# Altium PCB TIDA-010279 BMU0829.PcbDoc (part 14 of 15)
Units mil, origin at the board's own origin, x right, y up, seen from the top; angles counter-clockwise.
Board outline 11269.69 x 4438.98 mil, 4 copper layers (Top Layer, Signal Layer 1, Signal Layer 2, Bottom Layer), stack 61.6 mil thick; 1494 components, 725 nets, 3766 pads, 2728 vias.
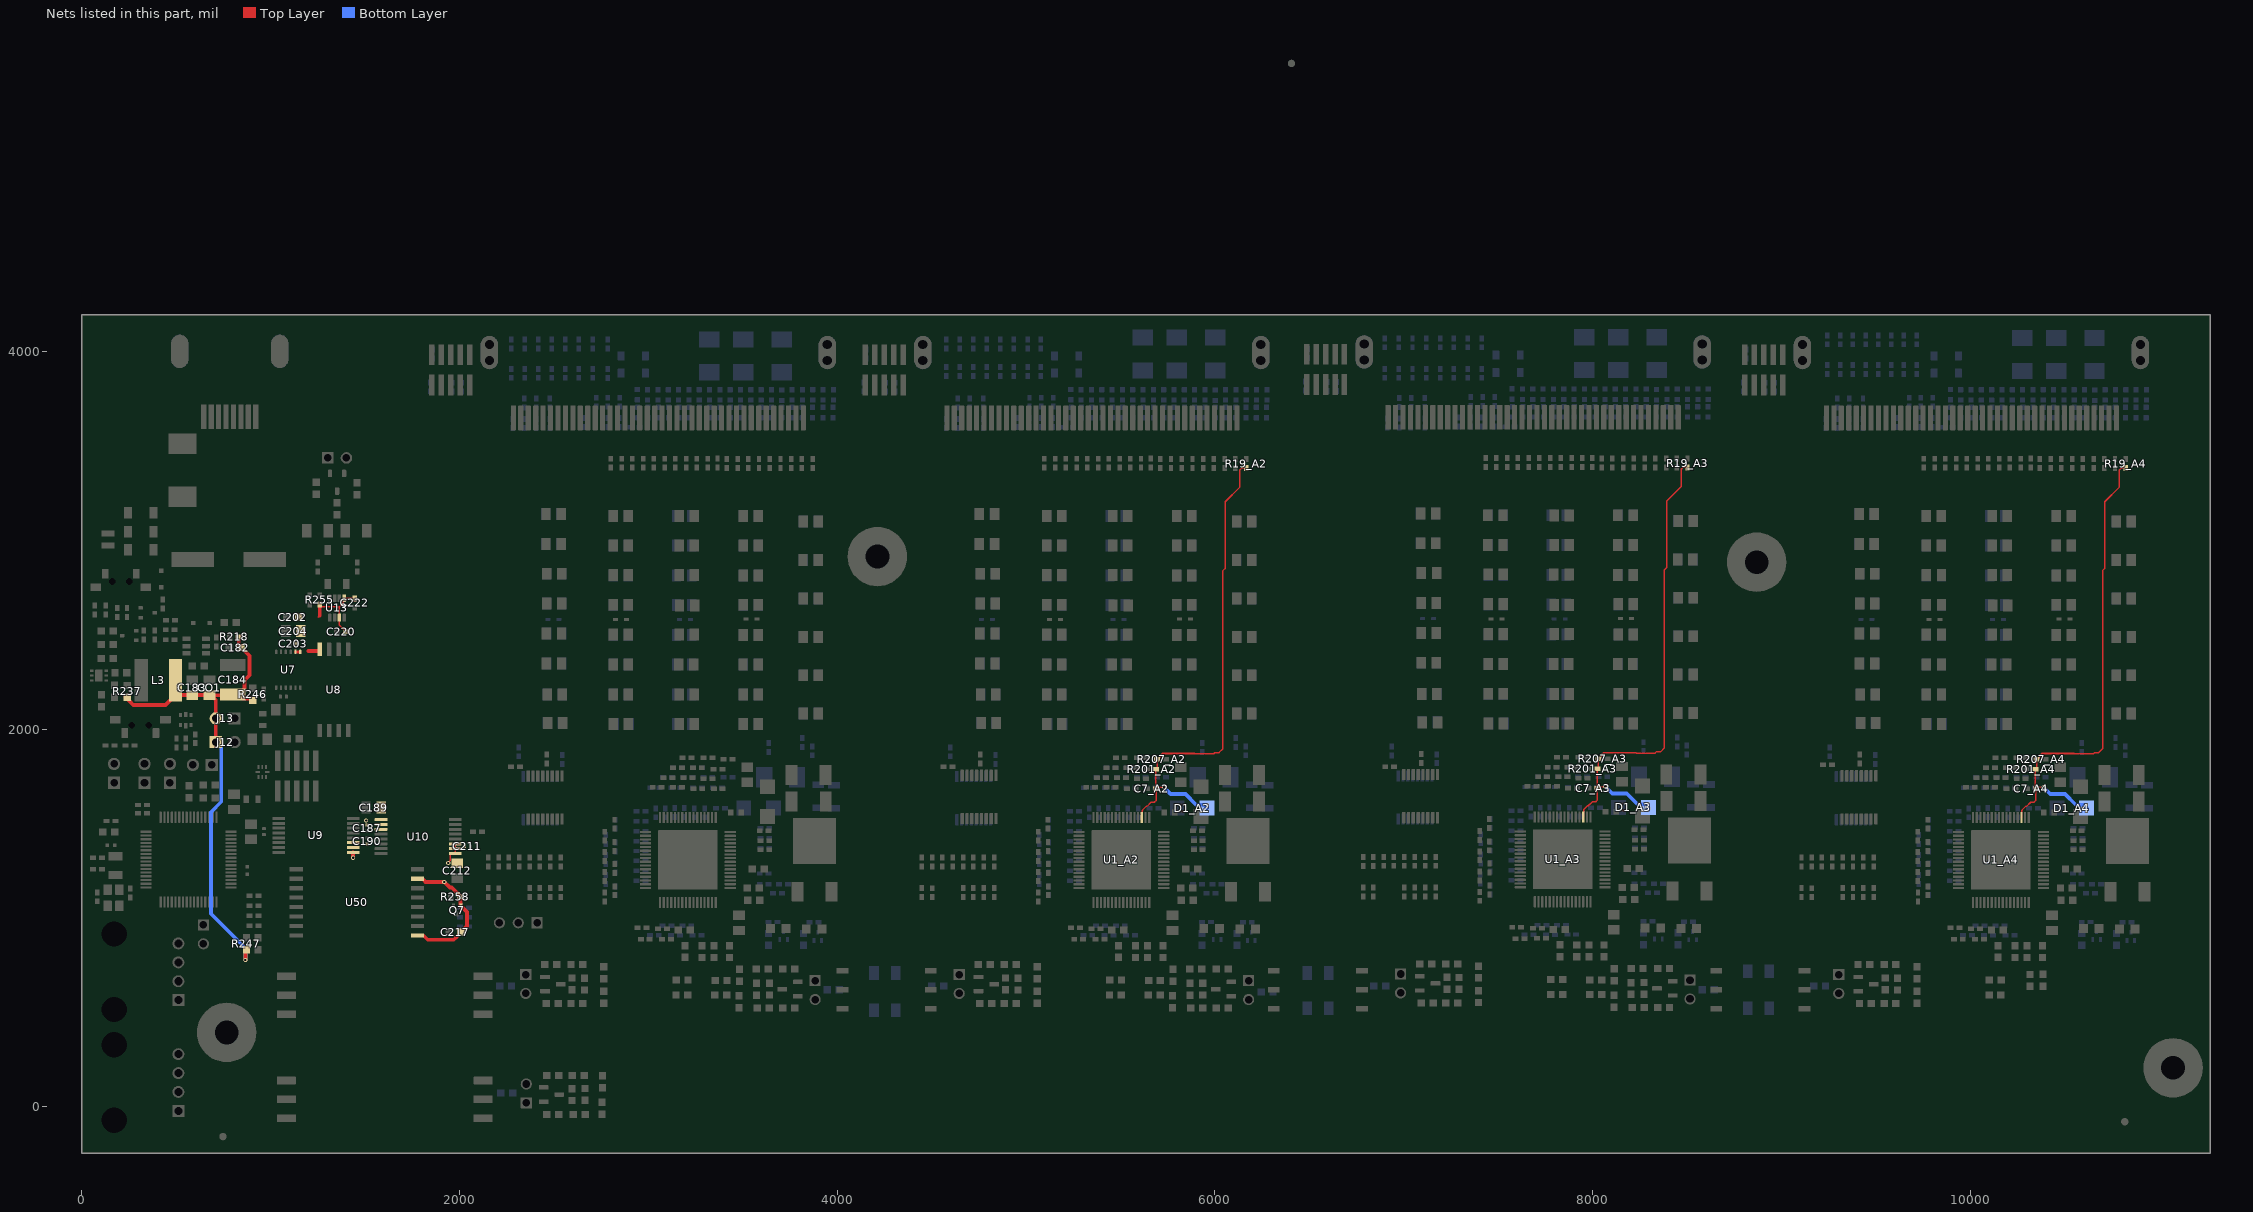
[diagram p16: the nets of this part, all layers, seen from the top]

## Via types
v1: diameter 22.01, hole 12.01, Top Layer to Bottom Layer, tented both sides, 2578 vias
v2: diameter 19.68, hole 7.87, Top Layer to Bottom Layer, tented both sides, 144 vias
v3: diameter 92.52, hole 49.21, Top Layer to Bottom Layer, 4 vias
v4: diameter 19.68, hole 7.87, Top Layer to Bottom Layer, 2 vias

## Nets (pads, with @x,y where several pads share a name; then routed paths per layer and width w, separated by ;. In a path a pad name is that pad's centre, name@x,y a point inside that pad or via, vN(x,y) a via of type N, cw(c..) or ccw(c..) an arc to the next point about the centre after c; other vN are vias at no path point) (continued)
VC18_A2: C7_A2.1 D1_A2.2 R19_A2.2 R201_A2.1 R207_A2.2 U1_A2.3 | length 2622.7
  Top Layer w8: U1_A2.3@5612.75,1531.37 5614.66,1533.27 5614.66,1567.53 5616.47,1569.35 5616.47,1572.07 5635.04,1590.64 5640.25,1590.64 5661.94,1612.33 5678.91,1612.33 5688.08,1621.5 C7_A2.1@5688.08,1683.81 ; R201_A2.1@5687.59,1787.63 R201_A2.1@5693.21,1793.25 ; C7_A2.1@5688.47,1692.33 5729.49,1692.33 v1(5729.7,1692.54) ; R19_A2.2@6165.29,3381.89 6141.48,3381.89 6132.1,3372.52 6132.1,3281.15 6054.11,3203.15 6054.11,2850.84 6042.45,2839.18 6042.45,1896.02 6021.97,1875.54 5999.07,1875.54 5993.22,1869.69 5894.24,1869.69 5893.16,1870.77 5719.79,1870.77 5712.83,1863.81 5712.83,1854.58 5697.81,1839.56 R207_A2.2@5693.87,1839.56 5693.21,1838.9 R201_A2.1@5693.21,1793.25 ; C7_A2.1@5688.73,1683.55 C7_A2.1@5688.73,1690.71 ; C7_A2.1@5688.73,1683.55 C7_A2.1@5688.73,1690.71 ; C7_A2.1@5688.73,1683.55 C7_A2.1@5688.73,1690.71 ; C7_A2.1@5688.73,1690.71 5687.97,1690.71 5687.32,1691.36 5687.32,1787.36 R201_A2.1@5693.21,1793.25
  Bottom Layer w20: v1(5729.7,1692.54) 5765.31,1656.93 5766.22,1656.93 5767.17,1655.98 5843.42,1655.98 5900.1,1599.3 5940.68,1599.3 D1_A2.2@5957.76,1582.22
VC18_A3: C7_A3.1 D1_A3.2 R19_A3.2 R201_A3.1 R207_A3.2 U1_A3.3 | length 2622.7
  Top Layer w8: U1_A3.3@7949.35,1534.57 7951.25,1536.48 7951.25,1570.74 7953.06,1572.55 7953.06,1575.28 7971.63,1593.85 7976.85,1593.85 7998.54,1615.54 8015.51,1615.54 8024.67,1624.7 C7_A3.1@8024.67,1687.01 ; R201_A3.1@8024.19,1790.84 R201_A3.1@8029.81,1796.46 ; C7_A3.1@8025.07,1695.54 8066.09,1695.54 v1(8066.3,1695.74) ; R19_A3.2@8501.88,3385.1 8478.07,3385.1 8468.7,3375.73 8468.7,3284.36 8390.7,3206.36 8390.7,2854.04 8379.05,2842.39 8379.05,1899.23 8358.57,1878.75 8335.67,1878.75 8329.82,1872.89 8230.84,1872.89 8229.76,1873.98 8056.38,1873.98 8049.43,1867.02 8049.43,1857.79 8034.41,1842.77 R207_A3.2@8030.47,1842.77 8029.81,1842.1 R201_A3.1@8029.81,1796.46 ; C7_A3.1@8025.33,1686.76 C7_A3.1@8025.33,1693.92 ; C7_A3.1@8025.33,1686.76 C7_A3.1@8025.33,1693.92 ; C7_A3.1@8025.33,1686.76 C7_A3.1@8025.33,1693.92 ; C7_A3.1@8025.33,1693.92 8024.57,1693.92 8023.92,1694.57 8023.92,1790.57 R201_A3.1@8029.81,1796.46
  Bottom Layer w20: v1(8066.3,1695.74) 8101.91,1660.14 8102.82,1660.14 8103.77,1659.19 8180.02,1659.19 8236.7,1602.51 8277.27,1602.51 D1_A3.2@8294.36,1585.42
VC18_A4: C7_A4.1 D1_A4.2 R19_A4.2 R201_A4.1 R207_A4.2 U1_A4.3 | length 2622.7
  Top Layer w8: U1_A4.3@10269.58,1531.37 10271.48,1533.27 10271.48,1567.54 10273.29,1569.35 10273.29,1572.07 10291.86,1590.64 10297.08,1590.64 10318.77,1612.33 10335.74,1612.33 10344.9,1621.5 C7_A4.1@10344.9,1683.81 ; R201_A4.1@10344.42,1787.63 R201_A4.1@10350.04,1793.25 ; C7_A4.1@10345.3,1692.33 10386.32,1692.33 v1(10386.53,1692.54) ; R19_A4.2@10822.11,3381.89 10798.3,3381.89 10788.93,3372.52 10788.93,3281.15 10710.93,3203.15 10710.93,2850.84 10699.28,2839.18 10699.28,1896.02 10678.79,1875.54 10655.9,1875.54 10650.05,1869.69 10551.07,1869.69 10549.99,1870.77 10376.61,1870.77 10369.66,1863.81 10369.66,1854.58 10354.64,1839.56 R207_A4.2@10350.7,1839.56 10350.04,1838.9 R201_A4.1@10350.04,1793.25 ; C7_A4.1@10345.56,1683.55 C7_A4.1@10345.56,1690.71 ; C7_A4.1@10345.56,1683.55 C7_A4.1@10345.56,1690.71 ; C7_A4.1@10345.56,1683.55 C7_A4.1@10345.56,1690.71 ; C7_A4.1@10345.56,1690.71 10344.8,1690.71 10344.15,1691.36 10344.15,1787.36 R201_A4.1@10350.04,1793.25
  Bottom Layer w20: v1(10386.53,1692.54) 10422.14,1656.93 10423.05,1656.93 10424,1655.98 10500.25,1655.98 10556.93,1599.3 10597.5,1599.3 D1_A4.2@10614.59,1582.22
VCC5V: C182.1 C183.1 C184.1 CO1.1 J12.1 J13.2 L3.2 R218.2 R237.1 R246.1 R247.1 | length 2777.1
  Top Layer w8: R247.1@866.53,826.47 R247.1@871.88,831.82
  Top Layer w20: R237.1@231.03,2172.36 231.03,2171.38 258.78,2143.63 258.78,2141.66 272.92,2127.52 443.55,2127.52 496.86,2180.83 L3.2@496.86,2206.04 ; L3.2@496.86,2257.6 L3.2@496.86,2206.04 ; CO1.1@676.04,2179.27 CO1.1@683.88,2179.27 ; CO1.1@676.04,2180.61 585.31,2180.61 522.29,2180.61 L3.2@496.86,2206.04 ; J12.1@709.8,1931.31 709.36,1931.75 J13.2@709.36,2056.51 709.36,2153.78 CO1.1@683.88,2179.27 ; C184.1@744.42,2193.5 C184.1@744.42,2194.83 ; C184.1@799.53,2182.8 834.96,2182.8 C184.1@807.09,2182.8 ; C184.1@807.09,2185.04 801.31,2179.27 CO1.1@683.88,2179.27 ; R218.2@830.92,2488.31 830.92,2443.74 842.77,2431.89 C182.1@843.75,2431.89 844.73,2431.89 888.45,2388.17 888.45,2284.95 862.52,2259.02 862.52,2216.01 856.46,2209.95 856.46,2204.29 C184.1@840.36,2188.19 ; C184.1@839.78,2181.63 839.78,2177.98 856.46,2161.3 897.75,2161.3 R246.1@905.51,2153.54 ; v1(866.53,777.52) 866.91,777.9 866.91,826.09 R247.1@866.53,826.47
  Bottom Layer w20: J12.1@709.8,1931.31 739.08,1902.03 739.08,1615.06 684.11,1560.08 684.11,1022.34 866.53,839.93 v1(866.53,777.52)
VDD5: C202.1 C203.2 C204.1 C220.2 C222.1 R255.2 U7.7 U7.8 U8.8 U13.3 U13.5 | length 544.6
  Top Layer w8: 1252.32,2593.41 1260.35,2601.44 ; R255.2@1260.35,2660.04 1260.35,2648.98 1364.4,2648.98 U13.3@1364.4,2590.08 1364.4,2549.92 1386.95,2527.37 1386.95,2523.44 1394.76,2515.62 C220.2@1398.7,2515.62 ; 1364.4,2647.26 1385.14,2667.99 1385.14,2687.58 U13.5@1389.99,2692.44 C222.1@1437.65,2692.44
  Top Layer w15: U7.8@1131.9,2408.32 U7.7@1157.49,2408.32
  Top Layer w20: C204.1@1161.18,2513.47 C204.1@1174.53,2500.13 ; 1200.79,2413.91 1258.39,2413.91 1260.2,2415.72 U8.8@1260.2,2421.91 ; 1260.35,2601.44 R255.2@1260.35,2648.98 ; C222.1@1446.1,2691.61 1446.1,2687.68 C222.1@1447.91,2685.87
VStage1_5V: C187.2 C189.1 C190.2 U9.9 U9.10 U9.11 U10.1 U10.2 U10.3 | length 50
  Top Layer w8: C189.1@1585.28,1584.65 C189.1@1600.28,1569.64
  Top Layer w20: v1(1437.01,1318.9) U9.9@1437.01,1347.44
  Bottom Layer w20: v1@1437.01,1318.67 v1(1437.01,1318.9)
  other v1: 1505.91,1515.89
VStage2_5V: C211.2 C212.1 C217.2 Q7.1 R258.2 U10.9 U10.10 U10.11 U50.1 U50.7 | length 803.2
  Top Layer w8: v1(1940.99,1290.66) 1940.99,1294.45 1950.95,1304.41 1950.95,1337.36 1955.02,1341.43 U10.9@1978.48,1341.43 ; U10.9@1975.37,1341.43 1978.35,1344.41 1978.35,1366.88 U10.10@1978.48,1367.02 1978.35,1367.15 1978.35,1392.48 U10.11@1978.48,1392.61
  Top Layer w20: U50.1@1811.02,905.51 1831.76,884.78 1970.1,884.78 1984.41,899.09 1984.41,900.75 2008.86,925.2 2010.83,925.2 2019.53,933.9 2019.53,936.85 2039.47,956.79 2039.47,1031.72 Q7.1@2011.18,1060 ; U50.7@1811.02,1200.79 1820.87,1190.94 v1(1919.29,1190.94) 1949.25,1160.99 1958.78,1160.99 2007.87,1111.89 R258.2@2007.87,1102.36 ; C212.1@1988.19,1290.63 C212.1@1994.69,1290.63 ; Q7.1@2006.14,1065.98 R258.2@2006.14,1102.36
pads on no net: FID1.1 FID2.1 FID3.1 H1.1 H2.1 H3.1 H4.1 H5.0 H6.0 H7.0 H8.0 H9.0 H10.0 H11.0 H12.0 J1_A1.9 J1_A2.9 J1_A3.9 J1_A4.9 J2_A1.9 J2_A1.29 J2_A1.41 J2_A1.42 J2_A2.9 J2_A2.29 J2_A2.41 J2_A2.42 J2_A3.9 J2_A3.29 J2_A3.41 J2_A3.42 J2_A4.9 J2_A4.29 J2_A4.41 J2_A4.42 J5.9 J5.10 J7.3 J7.4 J7.MH1 J7.MH2 J8.1 J8.2 J8.MH1 J8.MH2 J11.6 J11.8 LBL1.0 S1. S2. T1.2 T5.2 U2_A1.7 U2_A2.7 U2_A3.7 U2_A4.7 U3_A1.7 U3_A2.7 U3_A3.7 U3_A4.7 U6.5 U6.7@91.18,2265.47 U6.7@91.18,2300.91 U14.1 U14.3 U14.5 U50.6 U50.11
copper on no net:
  other v3: 519.07,3957.68 1048.6,3957.68 519.07,4042.32 1048.6,4042.32

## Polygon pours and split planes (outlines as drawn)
PGND on Top Layer "TOP_LAYER_PGND_P116" (solid, remove dead copper, pour order 116): 7.55,3722.03 7.55,-148.6 803.65,-148.6 803.65,3722.03
PGND on Top Layer "TOP_LAYER_PGND_P121" (solid, remove dead copper, pour order 121): 799.21,1567.46 799.21,1255.51 936.43,1255.51 936.43,1567.46
GND_A1 on Top Layer "Top Layer-001-AFE1" (solid, remove dead copper, pour order 92): 2106.72,423.23 4045.28,423.23 4045.28,4311.02 1838.84,4311.02 1838.84,4295.38 1811.02,4267.56 1811.02,3670.85 2089.13,3392.74 2117.9,3354.6
GND_A4 on Top Layer "TOP_LAYER_GND_A4_P132" (solid, pour order 132): 10236.22,423.23 10236.22,196.85 2795.28,196.85 2795.28,-98.43 2795.28,-88.58 10360.24,-88.58 10472.44,49.21 10472.44,423.23
GND_A4 on Top Layer "Top Layer-001-AFE1" (solid, remove dead copper, pour order 95): 9058.56,423.23 10997.12,423.23 10997.12,4311.02 8790.68,4311.02 8790.68,4295.38 8762.87,4267.56 8762.87,3670.85 9040.97,3392.74 9069.75,3354.6
PGND on Top Layer "TOP_LAYER_PGND_P118" (solid, remove dead copper, pour order 118): 793.4,2222.16 793.4,1535.29 1218.63,1535.29 1218.63,2222.16
DDGND on Top Layer "TOP_LAYER_DDGND_P120" (solid, remove dead copper, pour order 120): 1257.54,3005.58 1446.1,3005.58 1446.1,3273.89 1257.54,3273.89
PGND on Top Layer "TOP_LAYER_PGND_P119" (solid, remove dead copper, pour order 119): 793.4,2963.17 793.4,2839.08 1081.25,2839.08 1081.25,2963.17
VCC5V on Top Layer "TOP_LAYER_VCC5V_P115" (solid, remove dead copper, pour order 115): 465.33,2209.18 465.33,2151.48 871.28,2151.48 871.28,2209.18
PGND on Top Layer "TOP_LAYER_PGND_P113" (solid, remove dead copper, pour order 113): 739.35,2440.38 739.35,2331.15 873.21,2331.15 873.21,2370.08 808.56,2370.08 808.56,2440.38
PGND on Top Layer "TOP_LAYER_PGND_P112" (solid, remove dead copper, pour order 112): 655.22,2455.05 637.59,2455.05 637.59,2492.45 598.66,2492.45 598.66,2394.78 634.64,2394.78 637.59,2397.74 637.59,2432.78 655.22,2432.78
GND_A2 on Top Layer "Top Layer-001-AFE1" (solid, remove dead copper, pour order 93): 4401.73,423.23 6340.29,423.23 6340.29,4311.02 4133.86,4311.02 4133.86,4295.38 4106.04,4267.56 4106.04,3670.85 4384.15,3392.74 4412.92,3354.6
GND_A3 on Top Layer "Top Layer-001-AFE1" (solid, remove dead copper, pour order 94): 6738.33,426.44 8676.89,426.44 8676.89,4314.23 6470.45,4314.23 6470.45,4298.59 6442.64,4270.77 6442.64,3674.06 6720.74,3395.95 6749.52,3357.81
GND_A1 on Bottom Layer "Bot Layer-GND_AFE1" (solid, remove dead copper, pour order 104): 2096.87,423.23 4035.43,423.23 4035.43,4311.02 1829,4311.02 1829,4295.38 1801.18,4267.56 1801.18,3670.85 2079.29,3392.74 2108.06,3354.6
GND_A4 on Bottom Layer "BOTTOM_LAYER_GND_A4_P133" (solid, pour order 133): 10236.22,442.91 10236.22,196.85 2303.15,196.85 2303.15,-88.58 2312.99,-98.43 2795.28,-98.43 2795.28,-88.58 10360.24,-88.58 10472.44,49.21 10472.44,442.91
GND_Stage2 on Bottom Layer "BOTTOM_LAYER_GND_STAGE2_P129" (solid, pour order 129): 1957.42,1571.46 1948.76,1562.8 1948.76,1302.94 1915.78,1269.97 1837.55,1269.97 1837.55,911.7 1848.04,901.2 2071.78,901.2 2071.78,1568.13 2068.44,1571.46
GND_Stage1 on Bottom Layer "BOTTOM_LAYER_GND_STAGE1_P124" (solid, pour order 124): 1407.48,1633.86 1624.02,1633.86 1624.02,1299.21 1614.17,1289.37 1525.59,1289.37 1525.59,895.67 1505.91,875.98 1348.43,875.98 1348.43,1250 1407.48,1309.06
PGND on Bottom Layer "BOTTOM_LAYER_PGND_P117" (solid, remove dead copper, pour order 117): 157.48,2805.12 24.88,2672.52 24.88,-150 835.29,-150 835.29,2654.14 684.31,2805.12
GND_A3 on Bottom Layer "Bot Layer-GND_AFE1" (solid, remove dead copper, pour order 106): 6728.49,426.44 8667.05,426.44 8667.05,4314.23 6460.61,4314.23 6460.61,4298.59 6432.79,4270.77 6432.79,3674.06 6710.9,3395.95 6739.67,3357.81
GND_A4 on Bottom Layer "Bot Layer-GND_AFE1" (solid, remove dead copper, pour order 107): 9048.72,423.23 10987.28,423.23 10987.28,4311.02 8780.84,4311.02 8780.84,4295.38 8753.02,4267.56 8753.02,3670.85 9031.13,3392.74 9059.9,3354.6
GND_A2 on Bottom Layer "Bot Layer-GND_AFE1" (solid, remove dead copper, pour order 105): 4391.89,423.23 6330.45,423.23 6330.45,4311.02 4124.02,4311.02 4124.02,4295.38 4096.2,4267.56 4096.2,3670.85 4374.31,3392.74 4403.08,3354.6
GND_A1 on Signal Layer 1 "Signal_L2_001-AFE1" (solid, remove dead copper, pour order 100): 2096.87,413.39 4035.43,413.39 4035.43,4301.18 1829,4301.18 1829,4285.53 1801.18,4257.72 1801.18,3661.01 2079.29,3382.9 2108.06,3344.76
GND_A4 on Signal Layer 1 "SIGNAL_LAYER_1_GND_A4_P109" (solid, pour order 109): 10236.22,442.91 10236.22,196.85 2303.15,196.85 2303.15,-88.58 2312.99,-98.43 2795.28,-98.43 2795.28,-88.58 10360.24,-88.58 10472.44,49.21 10472.44,442.91
GND_Stage2 on Signal Layer 1 "SIGNAL_LAYER_1_GND_STAGE2_P128" (solid, pour order 128): 1957.48,1573.62 1948.82,1564.96 1948.82,1305.1 1915.84,1272.13 1837.61,1272.13 1837.61,913.86 1848.1,903.36 2071.84,903.36 2071.84,1570.29 2068.5,1573.62
GND_Stage1 on Signal Layer 1 "SIGNAL_LAYER_1_GND_STAGE1_P126" (solid, pour order 126): 1404.5,1634.44 1621.04,1634.44 1621.04,1299.8 1611.2,1289.95 1522.61,1289.95 1522.61,896.25 1502.93,876.57 1345.45,876.57 1345.45,1250.58 1404.5,1309.64
GND_A2 on Signal Layer 1 "Signal_L2_001-AFE1" (solid, remove dead copper, pour order 101): 4391.89,413.39 6330.45,413.39 6330.45,4301.18 4124.02,4301.18 4124.02,4285.53 4096.2,4257.72 4096.2,3661.01 4374.31,3382.9 4403.08,3344.76
GND_A3 on Signal Layer 1 "Signal_L2_001-AFE1" (solid, remove dead copper, pour order 102): 6728.49,416.59 8667.05,416.59 8667.05,4304.39 6460.61,4304.39 6460.61,4288.74 6432.79,4260.92 6432.79,3664.22 6710.9,3386.11 6739.67,3347.96
GND_A4 on Signal Layer 1 "Signal_L2_001-AFE1" (solid, remove dead copper, pour order 103): 9048.72,413.39 10987.28,413.39 10987.28,4301.18 8780.84,4301.18 8780.84,4285.53 8753.02,4257.72 8753.02,3661.01 9031.13,3382.9 9059.9,3344.76
GND_A1 on Signal Layer 2 "Signal_L3_001-AFE1" (solid, remove dead copper, pour order 96): 2097.3,423.79 4035.43,423.79 4035.43,4291.34 1829,4291.34 1829,4275.69 1815.09,4261.78 1815.09,3637.26 2079.29,3373.06 2108.06,3334.91 2108.06,3244.31
GND_A4 on Signal Layer 2 "SIGNAL_LAYER_2_GND_A4_P131" (solid, pour order 131): 10236.22,442.91 10236.22,196.85 2303.15,196.85 2303.15,-88.58 2312.99,-98.43 2795.28,-98.43 2795.28,-88.58 10360.24,-88.58 10472.44,49.21 10472.44,442.91
VStage2_5V on Signal Layer 2 "SIGNAL_LAYER_2_VSTAGE2_5V_P130" (solid, pour order 130): 1957.78,1572.53 1949.11,1563.87 1949.11,1304.01 1916.14,1271.03 1837.9,1271.03 1837.9,912.77 1848.4,902.27 2072.14,902.27 2072.14,1569.19 2068.8,1572.53
VStage1_5V on Signal Layer 2 "SIGNAL_LAYER_2_VSTAGE1_5V_P127" (solid, pour order 127): 1408.47,1633.52 1625.01,1633.52 1625.01,1298.87 1615.16,1289.03 1526.58,1289.03 1526.58,895.33 1506.9,875.64 1349.42,875.64 1349.42,1249.66 1408.47,1308.71
PGND on Signal Layer 2 "SIGNAL_LAYER_2_PGND_P114" (solid, remove dead copper, pour order 114): 49.21,3435.53 49.21,-127.95 840.88,-127.95 840.88,3435.53
GND_A2 on Signal Layer 2 "Signal_L3_001-AFE1" (solid, remove dead copper, pour order 97): 4392.31,423.79 6330.45,423.79 6330.45,4291.34 4124.02,4291.34 4124.02,4275.69 4110.11,4261.78 4110.11,3637.26 4374.31,3373.06 4403.08,3334.91 4403.08,3244.31
GND_A3 on Signal Layer 2 "Signal_L3_001-AFE1" (solid, remove dead copper, pour order 98): 6728.91,426.99 8667.05,426.99 8667.05,4294.55 6460.61,4294.55 6460.61,4278.9 6446.7,4264.99 6446.7,3640.47 6710.9,3376.27 6739.67,3338.12 6739.67,3247.51
GND_A4 on Signal Layer 2 "Signal_L3_001-AFE1" (solid, remove dead copper, pour order 99): 9049.14,423.79 10987.28,423.79 10987.28,4291.34 8780.84,4291.34 8780.84,4275.69 8766.93,4261.78 8766.93,3637.26 9031.13,3373.06 9059.9,3334.91 9059.9,3244.31

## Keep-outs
Keep-Out Layer:
  text ".Layer_Name" at 577,-858.49 h60

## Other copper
Top Layer:
  region net GND_Stage2: 1840.55,1269.68 1846.38,1275.51 1913.01,1275.51 1953.63,1234.89 2035.25,1234.89 2049.04,1248.68 2052.39,1245.33 2052.39,1180.85 1957.36,1180.85 1938.72,1199.49 1938.72,1217.38 1901.46,1254.64 1841.08,1254.64
  region net GND_Stage2: 1948.82,1574.8 2086.61,1574.8 2086.61,1181.1 2047.7,1181.1 2047.7,1302.55 2047.7,1417.32 1948.82,1417.32
  region net DDGND: 972.31,2654.14 972.31,2391.09 1115.75,2391.09 1115.75,2654.14
  region net NetC205_1: 996.3,2183.12 996.3,2069.86 1058.69,2069.86 1058.69,2183.12
  region net GND_Stage1: 1407.48,1624.02 1407.48,1417.32 1522.11,1417.32 1531.48,1407.95 1531.38,1407.85 1531.38,1374.74 1476.06,1319.42 1476.06,1293.9 1479.19,1290.77 1480.4,1291.98 1625.67,1291.98 1625.67,1326.41 1617.66,1334.41 1618.12,1334.86 1618.12,1451.14 1527.06,1451.14 1524.04,1454.16 1513.96,1467.45 1480.4,1467.45 1470.2,1477.64 1470.2,1542.86 1479.99,1552.65 1480.83,1551.81 1534.7,1551.81 1534.7,1619.52 1527.78,1626.43 1407.78,1626.43
  pour cut-out: 1407.48,1870.08 1230.31,1870.08 1171.26,1811.02 1171.26,875.98 1171.26,-236.22 1407.48,-236.22
  region net VStage1_5V: 1404.34,1403.95 1404.88,1403.41 1404.88,1338.58 1466.54,1338.58 1505.91,1377.95 1515.75,1387.8 1521.34,1387.8 1521.33,1387.81 1521.33,1405.67 1407.42,1405.67 1405.56,1407.52
  region net VStage1_5V: 1616.05,1618.41 1616.05,1461.42 1611.21,1460.24 1553.33,1460.24 1529.69,1483.87 1502.88,1483.87 1497.12,1489.63 1497.12,1523.57 1539.39,1523.57 1557.04,1541.22 1557.04,1618.41
  region net PGND: 1072.83,2234.25 1072.83,2175.2 1092.52,2155.51 1220.47,2155.51 1220.47,2234.25
  pour cut-out: 76.09,1185.12 44.69,1153.72 44.69,1056.01 68.92,1031.78 247.67,1031.78 277.18,1061.29 277.18,1151.43 245.03,1183.57
  pour cut-out: 974.41,2389.81 974.41,2236.18 1271.01,2236.18 1271.01,2387.09
  region net PGND: 1014.62,1455.98 1014.62,1339.29 1082.68,1339.29 1082.68,1455.98
  region net PGND: 1056.3,2053.8 1056.3,2003.4 1120.86,2003.4 1120.86,2053.8
  region net NetC213_1: 1024.28,1468.18 1024.28,1505.8 854.54,1505.8 854.54,1468.18
  pour cut-out: 63.5,1363.16 32.6,1332.27 32.6,1237.56 67.62,1202.54 238.54,1202.54 272,1236.01 272,1332.6 243.08,1361.52
  region net VDD5: 1128.69,2619.16 1128.69,2390.64 1268.68,2390.64 1268.68,2619.16
  region net VStage2_5V: 1937.47,1400.96 1937.47,1269.69 2033.57,1269.68 2033.57,1400.96
  pour cut-out: 849.09,1672.47 849.09,1595.35 961.71,1595.35 961.71,1671.44
  region net DDGND: 972.31,2645.2 1219,2645.2 1219,2675.78 972.31,2675.78
  pour cut-out: 1087.56,2843.23 1257.54,2843.23 1257.54,3435.53 1092.99,3435.53
  pour cut-out: 1255.26,2670.92 1255.26,2842.37 803.52,2842.37 803.52,2675.06
  pour cut-out: 976.11,2677.86 806.62,2677.86 806.63,2233.05 972.03,2233.05
  region net PGND: 851.87,1252.99 1023.99,1252.99 1023.99,1455.16 851.87,1455.16
  pour cut-out: 1830.71,834.1 2815.7,834.1 2905.55,744.25 3458.36,744.25 3458.36,747.7 3508.46,797.8 4063.31,797.8 4063.31,413.39 1830.71,413.39
  pour cut-out: 3405.51,1289.37 3612.2,1289.37 3622.05,1289.37 3641.73,1279.53 3641.73,1151.57 3622.05,1131.89 3503.94,1131.89 3464.57,1171.26 3464.57,1181.1 3405.51,1181.1 3405.51,1299.21 3395.67,1299.21 3395.67,1171.26 3405.51,1171.26 3454.72,1171.26 3503.94,1122.05 3622.05,1122.05 3651.57,1151.57 3651.57,1279.53 3622.05,1299.21 3612.2,1299.21 3405.51,1299.21
  region net CELL0_A1: 2371.07,2251.95 2495.94,2251.95 2495.94,1980.81 2371.07,1980.81
  region net CELL1_A1: 2370.87,2560.01 2495.74,2560.01 2495.74,2288.87 2370.87,2288.87
  region net CELL2_A1: 2370.87,2877.38 2495.74,2877.38 2495.74,2606.24 2370.87,2606.24
  region net CB0_A1: 2510.32,2251.95 2635.19,2251.95 2635.19,1980.81 2510.32,1980.81
  region net CB1_A1: 2511.71,2560.01 2636.58,2560.01 2636.58,2288.87 2511.71,2288.87
  region net CB2_A1: 2511.71,2877.38 2636.58,2877.38 2636.58,2606.24 2511.71,2606.24
  region net CELL4_A1: 2722.14,2242.64 2847.01,2242.64 2847.01,1971.5 2722.14,1971.5
  region net CELL5_A1: 2722.14,2559.36 2847.01,2559.36 2847.01,2288.22 2722.14,2288.22
  region net CB4_A1: 2863.18,2242.64 2988.05,2242.64 2988.05,1971.5 2863.18,1971.5
  region net CB5_A1: 2863.18,2559.36 2988.05,2559.36 2988.05,2288.22 2863.18,2288.22
  region net CELL6_A1: 2722.14,2876.08 2847.01,2876.08 2847.01,2604.94 2722.14,2604.94
  region net CB6_A1: 2863.18,2876.08 2988.05,2876.08 2988.05,2604.94 2863.18,2604.94
  region net CELL8_A1: 3077.16,2242.76 3202.03,2242.76 3202.03,1971.62 3077.16,1971.62
  region net CELL10_A1: 3077.16,2877.5 3202.03,2877.5 3202.03,2606.36 3077.16,2606.36
  region net CELL9_A1: 3079.07,2561.48 3203.94,2561.48 3203.94,2290.34 3079.07,2290.34
  region net CELL3_A1: 2495.75,2923.45 2370.87,2923.45 2370.87,3194.59 2495.75,3194.59
  region net CB3_A1: 2636.59,2923.45 2511.72,2923.45 2511.72,3194.59 2636.59,3194.59
  region net CELL7_A1: 2847.01,2921.66 2722.14,2921.66 2722.14,3192.8 2847.01,3192.8
  region net CB7_A1: 2988.05,2921.66 2863.18,2921.66 2863.18,3192.8 2988.05,3192.8
  region net CELL11_A1: 3077.16,3195.54 3202.03,3195.54 3202.03,2924.4 3077.16,2924.4
  region net CB8_A1: 3214.14,2242.76 3339.02,2242.76 3339.02,1971.62 3214.14,1971.62
  region net CB9_A1: 3214.14,2560.13 3339.02,2560.13 3339.02,2288.99 3214.14,2288.99
  pour cut-out: 4064.96,4246.79 4064.96,1201.43 3671.26,1201.43 3671.26,1481.76 3022.52,1481.76 3022.52,1138.81 2844.39,1141.69 2844.39,1136.74 2724.59,1016.94 2566.67,1016.94 2566.67,3341.05 2786.12,3341.05 2841.36,3396.3 2841.36,3512.81 2954.83,3512.81 2991.36,3549.34 2991.36,4243.33 2994.82,4246.79
  region net CELL12_A1: 3416.41,2241.78 3541.29,2241.78 3541.29,1970.64 3416.41,1970.64
  region net CELL13_A1: 3417.1,2560.13 3541.98,2560.13 3541.98,2288.99 3417.1,2288.99
  region net CB12_A1: 3554.09,2242.76 3678.96,2242.76 3678.96,1971.62 3554.09,1971.62
  region net CELL16_A1: 3772.15,2361.15 3860.17,2361.15 3860.17,1979.4 3772.15,1979.4
  region net CB16_A1: 3870.59,2358.65 3958.61,2358.65 3958.61,1979.4 3870.59,1979.4
  region net CB13_A1: 3554.09,2560.13 3678.96,2560.13 3678.96,2288.99 3554.09,2288.99
  region net CELL17_A1: 3771.83,2779.69 3859.85,2779.69 3859.85,2397.94 3771.83,2397.94
  region net CB17_A1: 3870.27,2777.19 3958.29,2777.19 3958.29,2397.94 3870.27,2397.94
  region net CELL0_A2: 4666.08,2251.95 4790.96,2251.95 4790.96,1980.81 4666.08,1980.81
  region net CELL1_A2: 4665.88,2560.01 4790.76,2560.01 4790.76,2288.87 4665.88,2288.87
  region net CB10_A1: 3214.14,2877.5 3339.02,2877.5 3339.02,2606.36 3214.14,2606.36
  region net CB11_A1: 3214.14,3194.87 3339.02,3194.87 3339.02,2923.73 3214.14,2923.73
  region net CELL14_A1: 3417.1,2877.5 3541.98,2877.5 3541.98,2606.36 3417.1,2606.36
  region net CELL15_A1: 3417.1,3195.54 3541.98,3195.54 3541.98,2924.4 3417.1,2924.4
  region net CB14_A1: 3554.09,2877.5 3678.96,2877.5 3678.96,2606.36 3554.09,2606.36
  region net CB15_A1: 3554.09,3194.87 3678.96,3194.87 3678.96,2923.73 3554.09,2923.73
  region net CELL18_A1: 3770.96,3198.23 3858.98,3198.23 3858.98,2816.48 3770.96,2816.48
  region net CB18_A1: 3869.4,3195.73 3957.42,3195.73 3957.42,2816.48 3869.4,2816.48
  region net CELL2_A2: 4665.88,2877.38 4790.76,2877.38 4790.76,2606.24 4665.88,2606.24
  region net CELL3_A2: 4790.76,2923.45 4665.89,2923.45 4665.89,3194.59 4790.76,3194.59
  pour cut-out: 4125.72,834.1 5110.71,834.1 5200.57,744.25 5753.37,744.25 5753.37,747.7 5803.48,797.8 6358.33,797.8 6358.33,413.39 4125.72,413.39
  pour cut-out: 5700.53,1289.37 5907.22,1289.37 5917.06,1289.37 5936.75,1279.53 5936.75,1151.57 5917.06,1131.89 5798.95,1131.89 5759.58,1171.26 5759.58,1181.1 5700.53,1181.1 5700.53,1299.21 5690.69,1299.21 5690.69,1171.26 5700.53,1171.26 5749.74,1171.26 5798.95,1122.05 5917.06,1122.05 5946.59,1151.57 5946.59,1279.53 5917.06,1299.21 5907.22,1299.21 5700.53,1299.21
  pour cut-out: 6462.32,837.31 7447.31,837.31 7537.16,747.45 8089.97,747.45 8089.97,750.9 8140.08,801.01 8694.92,801.01 8694.92,416.59 6462.32,416.59
  pour cut-out: 8037.12,1292.58 8243.82,1292.58 8253.66,1292.58 8273.34,1282.74 8273.34,1154.78 8253.66,1135.1 8135.55,1135.1 8096.18,1174.47 8096.18,1184.31 8037.12,1184.31 8037.12,1302.42 8027.28,1302.42 8027.28,1174.47 8037.12,1174.47 8086.34,1174.47 8135.55,1125.26 8253.66,1125.26 8283.19,1154.78 8283.19,1282.74 8253.66,1302.42 8243.82,1302.42 8037.12,1302.42
  pour cut-out: 8782.55,834.1 9767.54,834.1 9857.39,744.25 10236.22,744.25 10236.22,413.39 8782.55,413.39
  pour cut-out: 10357.35,1289.37 10564.05,1289.37 10573.89,1289.37 10593.57,1279.53 10593.57,1151.57 10573.89,1131.89 10455.78,1131.89 10416.41,1171.26 10416.41,1181.1 10357.35,1181.1 10357.35,1299.21 10347.51,1299.21 10347.51,1171.26 10357.35,1171.26 10406.57,1171.26 10455.78,1122.05 10573.89,1122.05 10603.42,1151.57 10603.42,1279.53 10573.89,1299.21 10564.05,1299.21 10357.35,1299.21
  region net CELL4_A2: 5017.15,2242.64 5142.03,2242.64 5142.03,1971.5 5017.15,1971.5
  region net CB0_A2: 4805.33,2251.95 4930.21,2251.95 4930.21,1980.81 4805.33,1980.81
  region net CB4_A2: 5158.19,2242.64 5283.07,2242.64 5283.07,1971.5 5158.19,1971.5
  region net CELL8_A2: 5372.17,2242.76 5497.05,2242.76 5497.05,1971.62 5372.17,1971.62
  region net CB8_A2: 5509.16,2242.76 5634.03,2242.76 5634.03,1971.62 5509.16,1971.62
  region net CELL12_A2: 5711.43,2241.78 5836.3,2241.78 5836.3,1970.64 5711.43,1970.64
  region net CB12_A2: 5849.1,2242.76 5973.98,2242.76 5973.98,1971.62 5849.1,1971.62
  region net CELL5_A2: 5017.15,2559.36 5142.03,2559.36 5142.03,2288.22 5017.15,2288.22
  region net CB1_A2: 4806.73,2560.01 4931.6,2560.01 4931.6,2288.87 4806.73,2288.87
  region net CELL6_A2: 5017.15,2876.08 5142.03,2876.08 5142.03,2604.94 5017.15,2604.94
  region net CB2_A2: 4806.73,2877.38 4931.6,2877.38 4931.6,2606.24 4806.73,2606.24
  region net CB5_A2: 5158.19,2559.36 5283.07,2559.36 5283.07,2288.22 5158.19,2288.22
  region net CB6_A2: 5158.19,2876.08 5283.07,2876.08 5283.07,2604.94 5158.19,2604.94
  region net CELL7_A2: 5142.03,2921.66 5017.15,2921.66 5017.15,3192.8 5142.03,3192.8
  region net CB3_A2: 4931.61,2923.45 4806.73,2923.45 4806.73,3194.59 4931.61,3194.59
  region net CB7_A2: 5283.07,2921.66 5158.19,2921.66 5158.19,3192.8 5283.07,3192.8
  region net CB9_A2: 5509.16,2560.13 5634.03,2560.13 5634.03,2288.99 5509.16,2288.99
  region net CELL9_A2: 5374.08,2561.48 5498.96,2561.48 5498.96,2290.34 5374.08,2290.34
  pour cut-out: 6359.98,4246.79 6359.98,1201.43 5966.28,1201.43 5966.28,1481.76 5317.54,1481.76 5317.54,1138.81 5139.4,1141.69 5139.4,1136.74 5019.61,1016.94 4861.69,1016.94 4861.69,3341.05 5081.14,3341.05 5136.38,3396.3 5136.38,3512.81 5249.85,3512.81 5286.38,3549.34 5286.38,4243.33 5289.84,4246.79
  region net CELL10_A2: 5372.17,2877.5 5497.05,2877.5 5497.05,2606.36 5372.17,2606.36
  region net CB10_A2: 5509.16,2877.5 5634.03,2877.5 5634.03,2606.36 5509.16,2606.36
  region net CELL13_A2: 5712.12,2560.13 5836.99,2560.13 5836.99,2288.99 5712.12,2288.99
  region net CB13_A2: 5849.1,2560.13 5973.98,2560.13 5973.98,2288.99 5849.1,2288.99
  region net CB14_A2: 5849.1,2877.5 5973.98,2877.5 5973.98,2606.36 5849.1,2606.36
  region net CB11_A2: 5509.16,3194.87 5634.03,3194.87 5634.03,2923.73 5509.16,2923.73
  region net CELL11_A2: 5372.17,3195.54 5497.05,3195.54 5497.05,2924.4 5372.17,2924.4
  region net CELL14_A2: 5712.12,2877.5 5836.99,2877.5 5836.99,2606.36 5712.12,2606.36
  region net CB15_A2: 5849.1,3194.87 5973.98,3194.87 5973.98,2923.73 5849.1,2923.73
  region net CELL15_A2: 5712.12,3195.54 5836.99,3195.54 5836.99,2924.4 5712.12,2924.4
  region net CB16_A2: 6165.61,2358.65 6253.62,2358.65 6253.62,1979.4 6165.61,1979.4
  region net CELL16_A2: 6067.17,2361.15 6155.19,2361.15 6155.19,1979.4 6067.17,1979.4
  region net CELL0_A3: 7002.68,2255.16 7127.56,2255.16 7127.56,1984.02 7002.68,1984.02
  region net CELL4_A3: 7353.75,2245.85 7478.62,2245.85 7478.62,1974.71 7353.75,1974.71
  region net CB0_A3: 7141.93,2255.16 7266.8,2255.16 7266.8,1984.02 7141.93,1984.02
  region net CB4_A3: 7494.79,2245.85 7619.67,2245.85 7619.67,1974.71 7494.79,1974.71
  region net CELL8_A3: 7708.77,2245.97 7833.65,2245.97 7833.65,1974.83 7708.77,1974.83
  region net CB17_A2: 6165.29,2777.19 6253.3,2777.19 6253.3,2397.94 6165.29,2397.94
  region net CELL17_A2: 6066.85,2779.69 6154.87,2779.69 6154.87,2397.94 6066.85,2397.94
  region net CELL1_A3: 7002.48,2563.22 7127.35,2563.22 7127.35,2292.08 7002.48,2292.08
  region net CB1_A3: 7143.32,2563.22 7268.2,2563.22 7268.2,2292.08 7143.32,2292.08
  region net CELL2_A3: 7002.48,2880.59 7127.35,2880.59 7127.35,2609.45 7002.48,2609.45
  region net CB2_A3: 7143.32,2880.59 7268.2,2880.59 7268.2,2609.45 7143.32,2609.45
  region net CB18_A2: 6164.42,3195.73 6252.43,3195.73 6252.43,2816.48 6164.42,2816.48
  region net CELL18_A2: 6065.98,3198.23 6154,3198.23 6154,2816.48 6065.98,2816.48
  region net CELL3_A3: 7127.36,2926.66 7002.48,2926.66 7002.48,3197.8 7127.36,3197.8
  region net CB3_A3: 7268.2,2926.66 7143.33,2926.66 7143.33,3197.8 7268.2,3197.8
  region net CB5_A3: 7494.79,2562.57 7619.67,2562.57 7619.67,2291.43 7494.79,2291.43
  region net CELL5_A3: 7353.75,2562.57 7478.62,2562.57 7478.62,2291.43 7353.75,2291.43
  region net CELL6_A3: 7353.75,2879.29 7478.62,2879.29 7478.62,2608.15 7353.75,2608.15
  region net CB6_A3: 7494.79,2879.29 7619.67,2879.29 7619.67,2608.15 7494.79,2608.15
  region net CELL9_A3: 7710.68,2564.69 7835.55,2564.69 7835.55,2293.55 7710.68,2293.55
  region net CELL10_A3: 7708.77,2880.71 7833.65,2880.71 7833.65,2609.57 7708.77,2609.57
  region net CELL7_A3: 7478.62,2924.86 7353.75,2924.86 7353.75,3196.01 7478.62,3196.01
  region net CB7_A3: 7619.67,2924.86 7494.79,2924.86 7494.79,3196.01 7619.67,3196.01
  region net CELL11_A3: 7708.77,3198.75 7833.65,3198.75 7833.65,2927.61 7708.77,2927.61
  region net CB8_A3: 7845.75,2245.97 7970.63,2245.97 7970.63,1974.83 7845.75,1974.83
  region net CELL12_A3: 8048.03,2244.99 8172.9,2244.99 8172.9,1973.85 8048.03,1973.85
  region net CB12_A3: 8185.7,2245.97 8310.57,2245.97 8310.57,1974.83 8185.7,1974.83
  region net CELL16_A3: 8403.77,2364.35 8491.78,2364.35 8491.78,1982.6 8403.77,1982.6
  region net CB16_A3: 8502.2,2361.85 8590.22,2361.85 8590.22,1982.6 8502.2,1982.6
  region net CELL0_A4: 9322.91,2251.95 9447.79,2251.95 9447.79,1980.81 9322.91,1980.81
  region net CB0_A4: 9462.16,2251.95 9587.03,2251.95 9587.03,1980.81 9462.16,1980.81
  region net CB9_A3: 7845.75,2563.34 7970.63,2563.34 7970.63,2292.2 7845.75,2292.2
  region net CELL13_A3: 8048.72,2563.34 8173.59,2563.34 8173.59,2292.2 8048.72,2292.2
  pour cut-out: 8696.57,4250 8696.57,1204.64 8302.87,1204.64 8302.87,1484.97 7654.13,1484.97 7654.13,1142.01 7476,1144.89 7476,1139.94 7356.2,1020.15 7198.29,1020.15 7198.29,3344.26 7417.73,3344.26 7472.98,3399.51 7472.98,3516.02 7586.44,3516.02 7622.98,3552.55 7622.98,4246.54 7626.44,4250
  region net CB13_A3: 8185.7,2563.34 8310.57,2563.34 8310.57,2292.2 8185.7,2292.2
  region net CB10_A3: 7845.75,2880.71 7970.63,2880.71 7970.63,2609.57 7845.75,2609.57
  region net CELL14_A3: 8048.72,2880.71 8173.59,2880.71 8173.59,2609.57 8048.72,2609.57
  region net CB11_A3: 7845.75,3198.08 7970.63,3198.08 7970.63,2926.93 7845.75,2926.93
  region net CELL15_A3: 8048.72,3198.75 8173.59,3198.75 8173.59,2927.61 8048.72,2927.61
  region net CB14_A3: 8185.7,2880.71 8310.57,2880.71 8310.57,2609.57 8185.7,2609.57
  region net CELL18_A3: 8402.58,3201.44 8490.59,3201.44 8490.59,2819.69 8402.58,2819.69
  region net CB15_A3: 8185.7,3198.08 8310.57,3198.08 8310.57,2926.93 8185.7,2926.93
  region net CB17_A3: 8501.88,2780.4 8589.9,2780.4 8589.9,2401.15 8501.88,2401.15
  region net CELL17_A3: 8403.45,2782.9 8491.46,2782.9 8491.46,2401.15 8403.45,2401.15
  region net CELL1_A4: 9322.71,2560.01 9447.58,2560.01 9447.58,2288.87 9322.71,2288.87
  region net CB1_A4: 9463.55,2560.01 9588.43,2560.01 9588.43,2288.87 9463.55,2288.87
  region net CELL2_A4: 9322.71,2877.38 9447.58,2877.38 9447.58,2606.24 9322.71,2606.24
  region net CB18_A3: 8501.01,3198.94 8589.03,3198.94 8589.03,2819.69 8501.01,2819.69
  region net CB2_A4: 9463.55,2877.38 9588.43,2877.38 9588.43,2606.24 9463.55,2606.24
  region net CELL3_A4: 9447.59,2923.45 9322.71,2923.45 9322.71,3194.59 9447.59,3194.59
  region net CB3_A4: 9588.43,2923.45 9463.56,2923.45 9463.56,3194.59 9588.43,3194.59
  region net CELL4_A4: 9673.98,2242.64 9798.85,2242.64 9798.85,1971.5 9673.98,1971.5
  region net CB4_A4: 9815.02,2242.64 9939.89,2242.64 9939.89,1971.5 9815.02,1971.5
  region net CELL5_A4: 9673.98,2559.36 9798.85,2559.36 9798.85,2288.22 9673.98,2288.22
  region net CB5_A4: 9815.02,2559.36 9939.89,2559.36 9939.89,2288.22 9815.02,2288.22
  region net CELL8_A4: 10029,2242.76 10153.88,2242.76 10153.88,1971.62 10029,1971.62
  region net CB8_A4: 10165.98,2242.76 10290.86,2242.76 10290.86,1971.62 10165.98,1971.62
  region net CELL12_A4: 10368.26,2241.78 10493.13,2241.78 10493.13,1970.64 10368.26,1970.64
  region net CB12_A4: 10505.93,2242.76 10630.8,2242.76 10630.8,1971.62 10505.93,1971.62
  region net CB13_A4: 10505.93,2560.13 10630.8,2560.13 10630.8,2288.99 10505.93,2288.99
  region net CELL13_A4: 10368.95,2560.13 10493.82,2560.13 10493.82,2288.99 10368.95,2288.99
  region net CB16_A4: 10822.43,2358.65 10910.45,2358.65 10910.45,1979.4 10822.43,1979.4
  region net CELL16_A4: 10724,2361.15 10812.01,2361.15 10812.01,1979.4 10724,1979.4
  region net CELL6_A4: 9673.98,2876.08 9798.85,2876.08 9798.85,2604.94 9673.98,2604.94
  region net CB6_A4: 9815.02,2876.08 9939.89,2876.08 9939.89,2604.94 9815.02,2604.94
  region net CB9_A4: 10165.98,2560.13 10290.86,2560.13 10290.86,2288.99 10165.98,2288.99
  region net CELL9_A4: 10030.91,2561.48 10155.78,2561.48 10155.78,2290.34 10030.91,2290.34
  region net CB10_A4: 10165.98,2877.5 10290.86,2877.5 10290.86,2606.36 10165.98,2606.36
  region net CELL10_A4: 10029,2877.5 10153.88,2877.5 10153.88,2606.36 10029,2606.36
  region net CELL7_A4: 9798.85,2921.66 9673.98,2921.66 9673.98,3192.8 9798.85,3192.8
  region net CB7_A4: 9939.89,2921.66 9815.02,2921.66 9815.02,3192.8 9939.89,3192.8
  region net CB11_A4: 10165.98,3194.87 10290.86,3194.87 10290.86,2923.73 10165.98,2923.73
  region net CELL11_A4: 10029,3195.54 10153.88,3195.54 10153.88,2924.4 10029,2924.4
  pour cut-out: 11016.8,4246.79 11016.8,1201.43 10623.1,1201.43 10623.1,1481.76 9974.36,1481.76 9974.36,1138.81 9796.23,1141.69 9796.23,1136.74 9676.43,1016.94 9518.52,1016.94 9518.52,3341.05 9737.96,3341.05 9793.21,3396.3 9793.21,3512.81 9906.67,3512.81 9943.21,3549.34 9943.21,4243.33 9946.67,4246.79
  region net CELL14_A4: 10368.95,2877.5 10493.82,2877.5 10493.82,2606.36 10368.95,2606.36
  region net CB14_A4: 10505.93,2877.5 10630.8,2877.5 10630.8,2606.36 10505.93,2606.36
  region net CB17_A4: 10822.11,2777.19 10910.13,2777.19 10910.13,2397.94 10822.11,2397.94
  region net CELL17_A4: 10723.68,2779.69 10811.69,2779.69 10811.69,2397.94 10723.68,2397.94
  region net CB15_A4: 10505.93,3194.87 10630.8,3194.87 10630.8,2923.73 10505.93,2923.73
  region net CELL15_A4: 10368.95,3195.54 10493.82,3195.54 10493.82,2924.4 10368.95,2924.4
  region net CB18_A4: 10821.24,3195.73 10909.26,3195.73 10909.26,2816.48 10821.24,2816.48
  region net CELL18_A4: 10722.81,3198.23 10810.82,3198.23 10810.82,2816.48 10722.81,2816.48
  text ".Layer_Name" at 577,-858.49 h60
Signal Layer 1:
  pour cut-out: 1840.55,833.54 2289.31,833.54 2289.31,413.39 1840.55,413.39
  pour cut-out: 2841.36,1529.6 2841.36,1159.94 2855.81,1159.94 2883.86,1131.89 2925.6,1131.89 2925.6,1533.02 2914.1,1544.52 2914,1544.42 2842.52,1544.42
  pour cut-out: 3933.27,791.96 4064.96,791.96 4064.96,417.95 3933.27,417.95
  pour cut-out: 4135.57,833.54 4584.33,833.54 4584.33,413.39 4135.57,413.39
  pour cut-out: 2997.85,1679.42 2997.85,1625.79 3019.31,1604.33 3456.15,1604.33 3456.15,1715.62 3449.41,1722.36 3404.88,1722.36 3388.65,1706.13 3388.65,1681.23 2999.65,1681.23 2999.06,1680.64
  pour cut-out: 3366.14,1555.12 3363.84,1552.82 3363.84,1507.74 3404.88,1507.74 3412.28,1515.14 3412.28,1558.93 3363.84,1558.93
  pour cut-out: 5136.38,1529.6 5136.38,1159.94 5150.83,1159.94 5178.87,1131.89 5220.61,1131.89 5220.61,1533.02 5209.11,1544.52 5209.02,1544.42 5137.53,1544.42
  pour cut-out: 6228.28,791.96 6359.98,791.96 6359.98,417.95 6228.28,417.95
  pour cut-out: 6472.16,836.75 6920.93,836.75 6920.93,416.59 6472.16,416.59
  pour cut-out: 5292.87,1679.42 5292.87,1625.79 5314.32,1604.33 5751.16,1604.33 5751.16,1715.62 5744.42,1722.36 5699.9,1722.36 5683.67,1706.13 5683.67,1681.23 5294.67,1681.23 5294.08,1680.64
  pour cut-out: 5661.16,1555.12 5658.86,1552.82 5658.86,1507.74 5699.9,1507.74 5707.3,1515.14 5707.3,1558.93 5658.86,1558.93
  pour cut-out: 3129.92,3612.2 3132,3610.13 3132,3494.09 3884.4,3494.09 3947.94,3557.64 3854,3651.57 3181.27,3651.57 3178.81,3649.12
  pour cut-out: 3219.12,4251.97 3789.37,4251.97 3789.37,4133.86 3211.74,4133.86
  pour cut-out: 5424.94,3612.2 5427.01,3610.13 5427.01,3494.09 6179.42,3494.09 6242.96,3557.64 6149.02,3651.57 5476.29,3651.57 5473.83,3649.12
  pour cut-out: 5514.14,4251.97 6084.39,4251.97 6084.39,4133.86 5506.75,4133.86
  pour cut-out: 7472.98,1532.81 7472.98,1163.14 7487.42,1163.14 7515.47,1135.1 7557.21,1135.1 7557.21,1536.23 7545.71,1547.73 7545.61,1547.63 7474.13,1547.63
  pour cut-out: 8564.88,795.17 8696.57,795.17 8696.57,421.16 8564.88,421.16
  pour cut-out: 8792.39,833.54 9241.16,833.54 9241.16,413.39 8792.39,413.39
  pour cut-out: 7629.46,1682.63 7629.46,1628.99 7650.92,1607.54 8087.76,1607.54 8087.76,1718.83 8081.02,1725.57 8036.49,1725.57 8020.26,1709.34 8020.26,1684.43 7631.27,1684.43 7630.68,1683.84
  pour cut-out: 7997.75,1558.33 7995.46,1556.03 7995.46,1510.95 8036.49,1510.95 8043.9,1518.35 8043.9,1562.14 7995.46,1562.14
  pour cut-out: 9793.21,1529.6 9793.21,1159.94 9807.65,1159.94 9835.7,1131.89 9877.44,1131.89 9877.44,1533.02 9865.94,1544.52 9865.84,1544.42 9794.36,1544.42
  pour cut-out: 10885.11,791.96 11016.8,791.96 11016.8,417.95 10885.11,417.95
  pour cut-out: 9949.69,1679.42 9949.69,1625.79 9971.15,1604.33 10407.99,1604.33 10407.99,1715.62 10401.25,1722.36 10356.72,1722.36 10340.49,1706.13 10340.49,1681.23 9951.5,1681.23 9950.91,1680.64
  pour cut-out: 10317.98,1555.12 10315.69,1552.82 10315.69,1507.74 10356.72,1507.74 10364.12,1515.14 10364.12,1558.93 10315.69,1558.93
  pour cut-out: 7850.73,4255.18 8420.98,4255.18 8420.98,4137.07 7843.35,4137.07
  pour cut-out: 7761.53,3615.41 7763.61,3613.34 7763.61,3497.3 8516.01,3497.3 8579.55,3560.84 8485.61,3654.78 7812.88,3654.78 7810.42,3652.33
  pour cut-out: 10081.76,3612.2 10083.84,3610.13 10083.84,3494.09 10836.24,3494.09 10899.78,3557.64 10805.84,3651.57 10133.11,3651.57 10130.65,3649.12
  pour cut-out: 10170.96,4251.97 10741.21,4251.97 10741.21,4133.86 10163.58,4133.86
Signal Layer 2:
  pour cut-out: 1850.39,833.54 2287.01,833.54 2287.01,423.23 1850.39,423.23
  pour cut-out: 2841.36,1529.6 2841.36,1159.94 2855.81,1159.94 2883.86,1131.89 2925.6,1131.89 2925.6,1533.02 2914.1,1544.52 2914,1544.42 2842.52,1544.42
  pour cut-out: 3366.14,1555.12 3363.84,1552.82 3363.84,1507.74 3404.88,1507.74 3412.28,1515.14 3412.28,1558.93 3363.84,1558.93
  pour cut-out: 2997.85,1679.42 2997.85,1625.79 3019.31,1604.33 3456.15,1604.33 3456.15,1715.62 3449.41,1722.36 3404.88,1722.36 3388.65,1706.13 3388.65,1681.23 2999.65,1681.23 2999.06,1680.64
  pour cut-out: 3933.27,791.96 4074.8,791.96 4074.8,424.88 4067.87,417.95 3933.27,417.95
  pour cut-out: 4145.41,833.54 4582.03,833.54 4582.03,423.23 4145.41,423.23
  pour cut-out: 6228.28,791.96 6369.82,791.96 6369.82,424.88 6362.89,417.95 6228.28,417.95
  pour cut-out: 6482.01,836.75 6918.63,836.75 6918.63,426.44 6482.01,426.44
  pour cut-out: 5136.38,1529.6 5136.38,1159.94 5150.83,1159.94 5178.87,1131.89 5220.61,1131.89 5220.61,1533.02 5209.11,1544.52 5209.02,1544.42 5137.53,1544.42
  pour cut-out: 5661.16,1555.12 5658.86,1552.82 5658.86,1507.74 5699.9,1507.74 5707.3,1515.14 5707.3,1558.93 5658.86,1558.93
  pour cut-out: 5292.87,1679.42 5292.87,1625.79 5314.32,1604.33 5751.16,1604.33 5751.16,1715.62 5744.42,1722.36 5699.9,1722.36 5683.67,1706.13 5683.67,1681.23 5294.67,1681.23 5294.08,1680.64
  pour cut-out: 3129.92,3612.2 3132,3610.13 3132,3494.09 3884.4,3494.09 3947.94,3557.64 3854,3651.57 3181.27,3651.57 3178.81,3649.12
  pour cut-out: 3219.12,4251.97 3789.37,4251.97 3789.37,4133.86 3211.74,4133.86
  pour cut-out: 5424.94,3612.2 5427.01,3610.13 5427.01,3494.09 6179.42,3494.09 6242.96,3557.64 6149.02,3651.57 5476.29,3651.57 5473.83,3649.12
  pour cut-out: 5514.14,4251.97 6084.39,4251.97 6084.39,4133.86 5506.75,4133.86
  pour cut-out: 7472.98,1532.81 7472.98,1163.14 7487.42,1163.14 7515.47,1135.1 7557.21,1135.1 7557.21,1536.23 7545.71,1547.73 7545.61,1547.63 7474.13,1547.63
  pour cut-out: 7997.75,1558.33 7995.46,1556.03 7995.46,1510.95 8036.49,1510.95 8043.9,1518.35 8043.9,1562.14 7995.46,1562.14
  pour cut-out: 7629.46,1682.63 7629.46,1628.99 7650.92,1607.54 8087.76,1607.54 8087.76,1718.83 8081.02,1725.57 8036.49,1725.57 8020.26,1709.34 8020.26,1684.43 7631.27,1684.43 7630.68,1683.84
  pour cut-out: 8564.88,795.17 8706.42,795.17 8706.42,428.09 8699.49,421.16 8564.88,421.16
  pour cut-out: 8802.24,833.54 9238.86,833.54 9238.86,423.23 8802.24,423.23
  pour cut-out: 10885.11,791.96 11026.65,791.96 11026.65,424.88 11019.72,417.95 10885.11,417.95
  pour cut-out: 9793.21,1529.6 9793.21,1159.94 9807.65,1159.94 9835.7,1131.89 9877.44,1131.89 9877.44,1533.02 9865.94,1544.52 9865.84,1544.42 9794.36,1544.42
  pour cut-out: 10317.98,1555.12 10315.69,1552.82 10315.69,1507.74 10356.72,1507.74 10364.12,1515.14 10364.12,1558.93 10315.69,1558.93
  pour cut-out: 9949.69,1679.42 9949.69,1625.79 9971.15,1604.33 10407.99,1604.33 10407.99,1715.62 10401.25,1722.36 10356.72,1722.36 10340.49,1706.13 10340.49,1681.23 9951.5,1681.23 9950.91,1680.64
  pour cut-out: 7761.53,3615.41 7763.61,3613.34 7763.61,3497.3 8516.01,3497.3 8579.55,3560.84 8485.61,3654.78 7812.88,3654.78 7810.42,3652.33
  pour cut-out: 7850.73,4255.18 8420.98,4255.18 8420.98,4137.07 7843.35,4137.07
  pour cut-out: 10081.76,3612.2 10083.84,3610.13 10083.84,3494.09 10836.24,3494.09 10899.78,3557.64 10805.84,3651.57 10133.11,3651.57 10130.65,3649.12
  pour cut-out: 10170.96,4251.97 10741.21,4251.97 10741.21,4133.86 10163.58,4133.86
